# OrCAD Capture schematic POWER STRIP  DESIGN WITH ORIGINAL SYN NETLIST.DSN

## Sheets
1 PAGE2: size Custom; title: Power Micro Board; rev: <A>; note: Power Micro Board
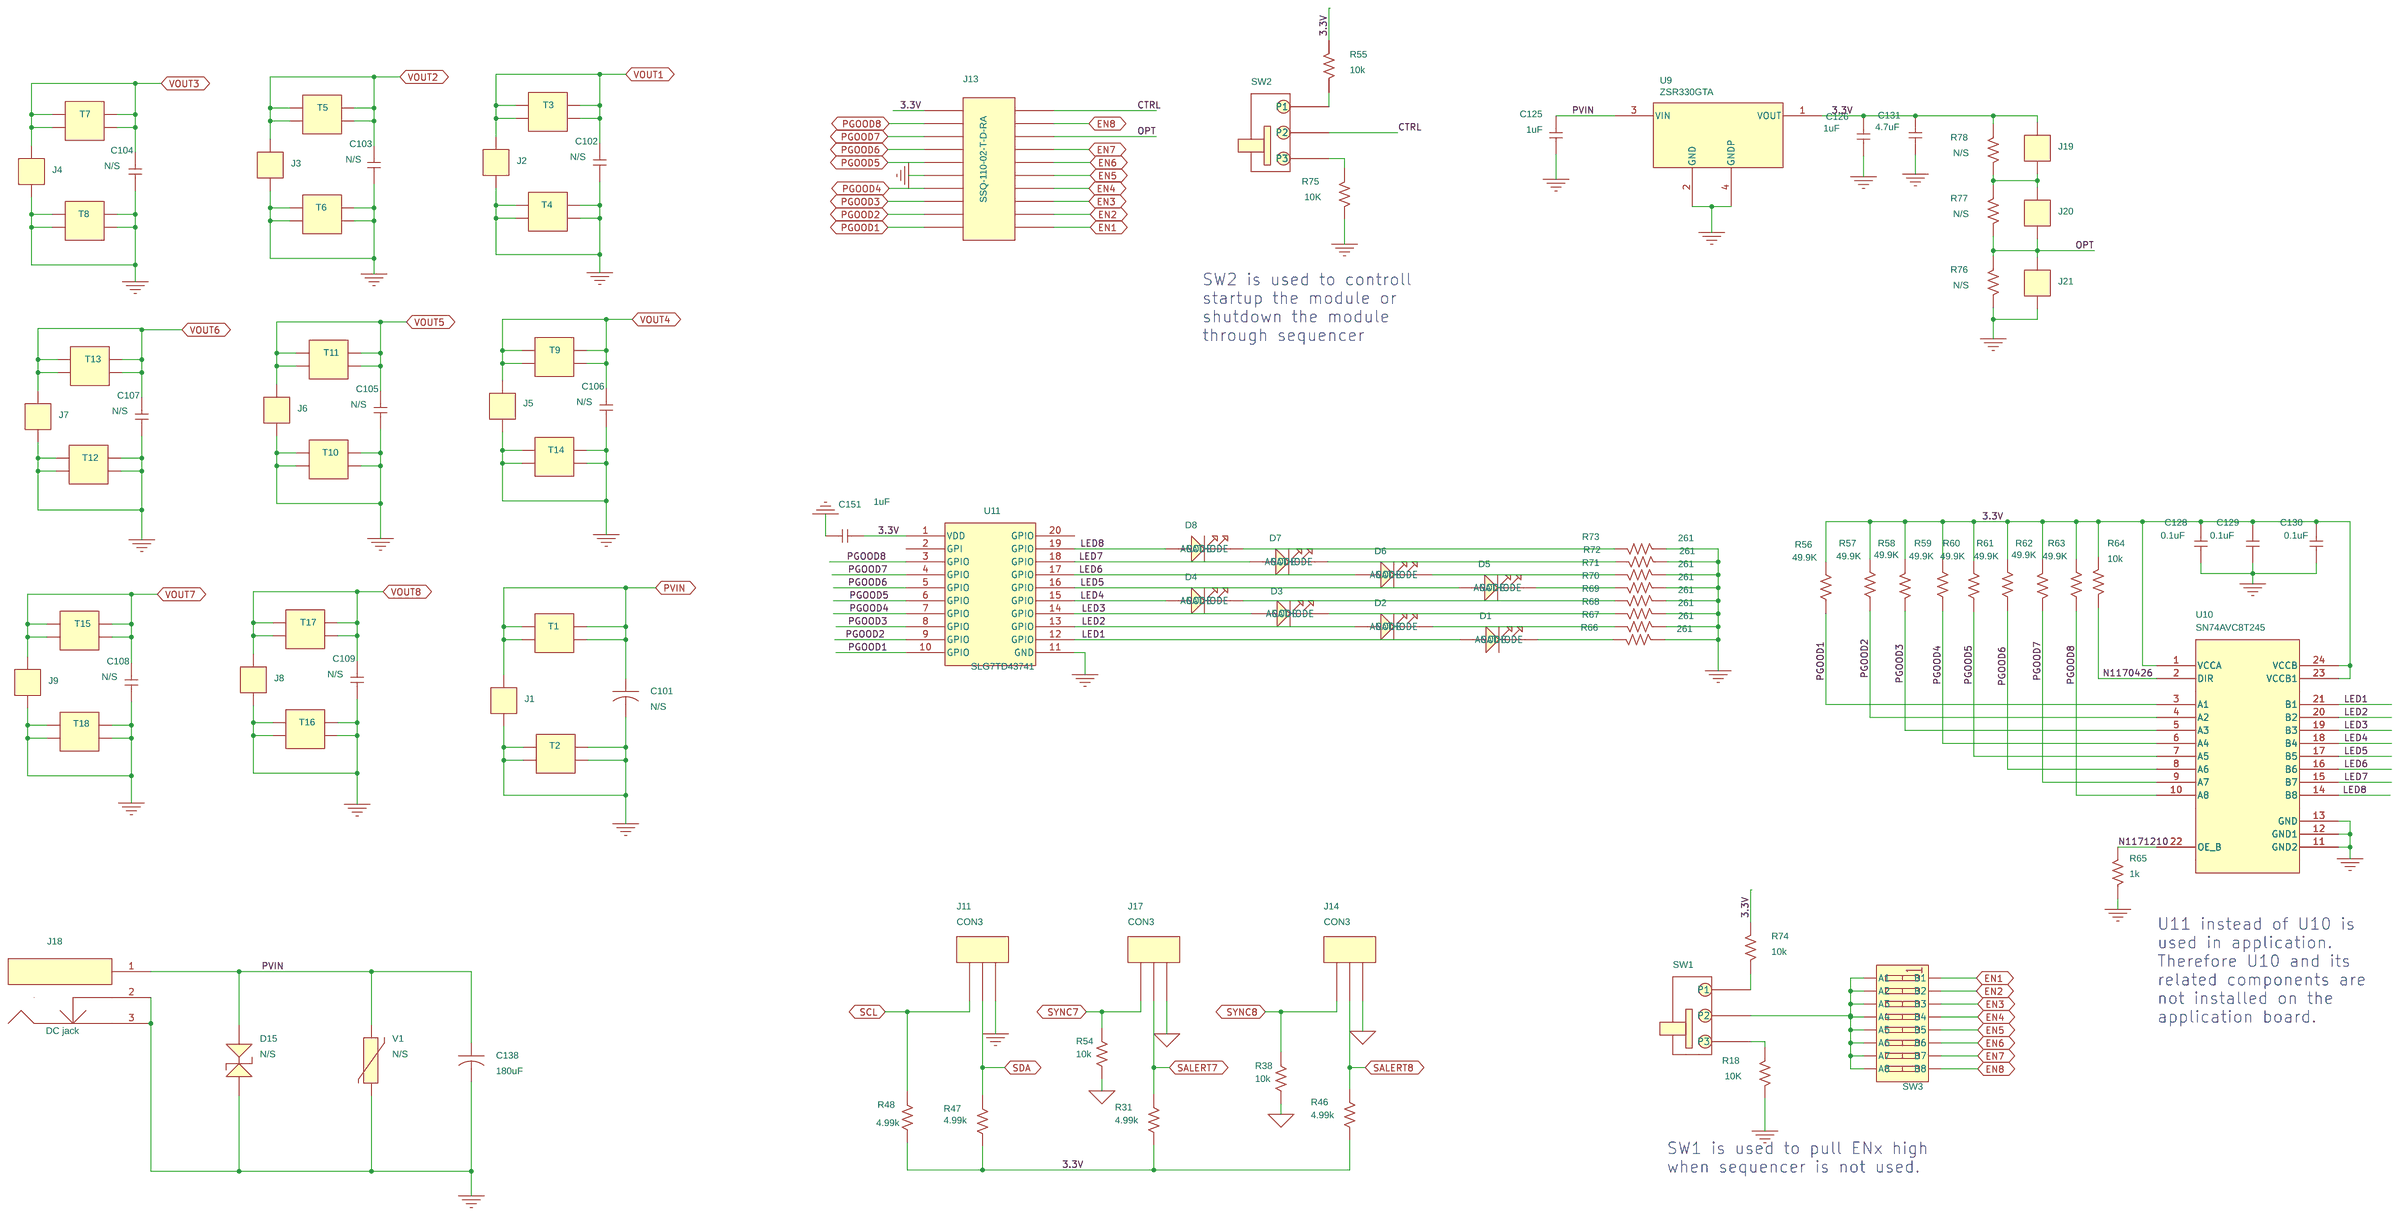
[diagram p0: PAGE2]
2 PAGE1: size Custom; rev: A
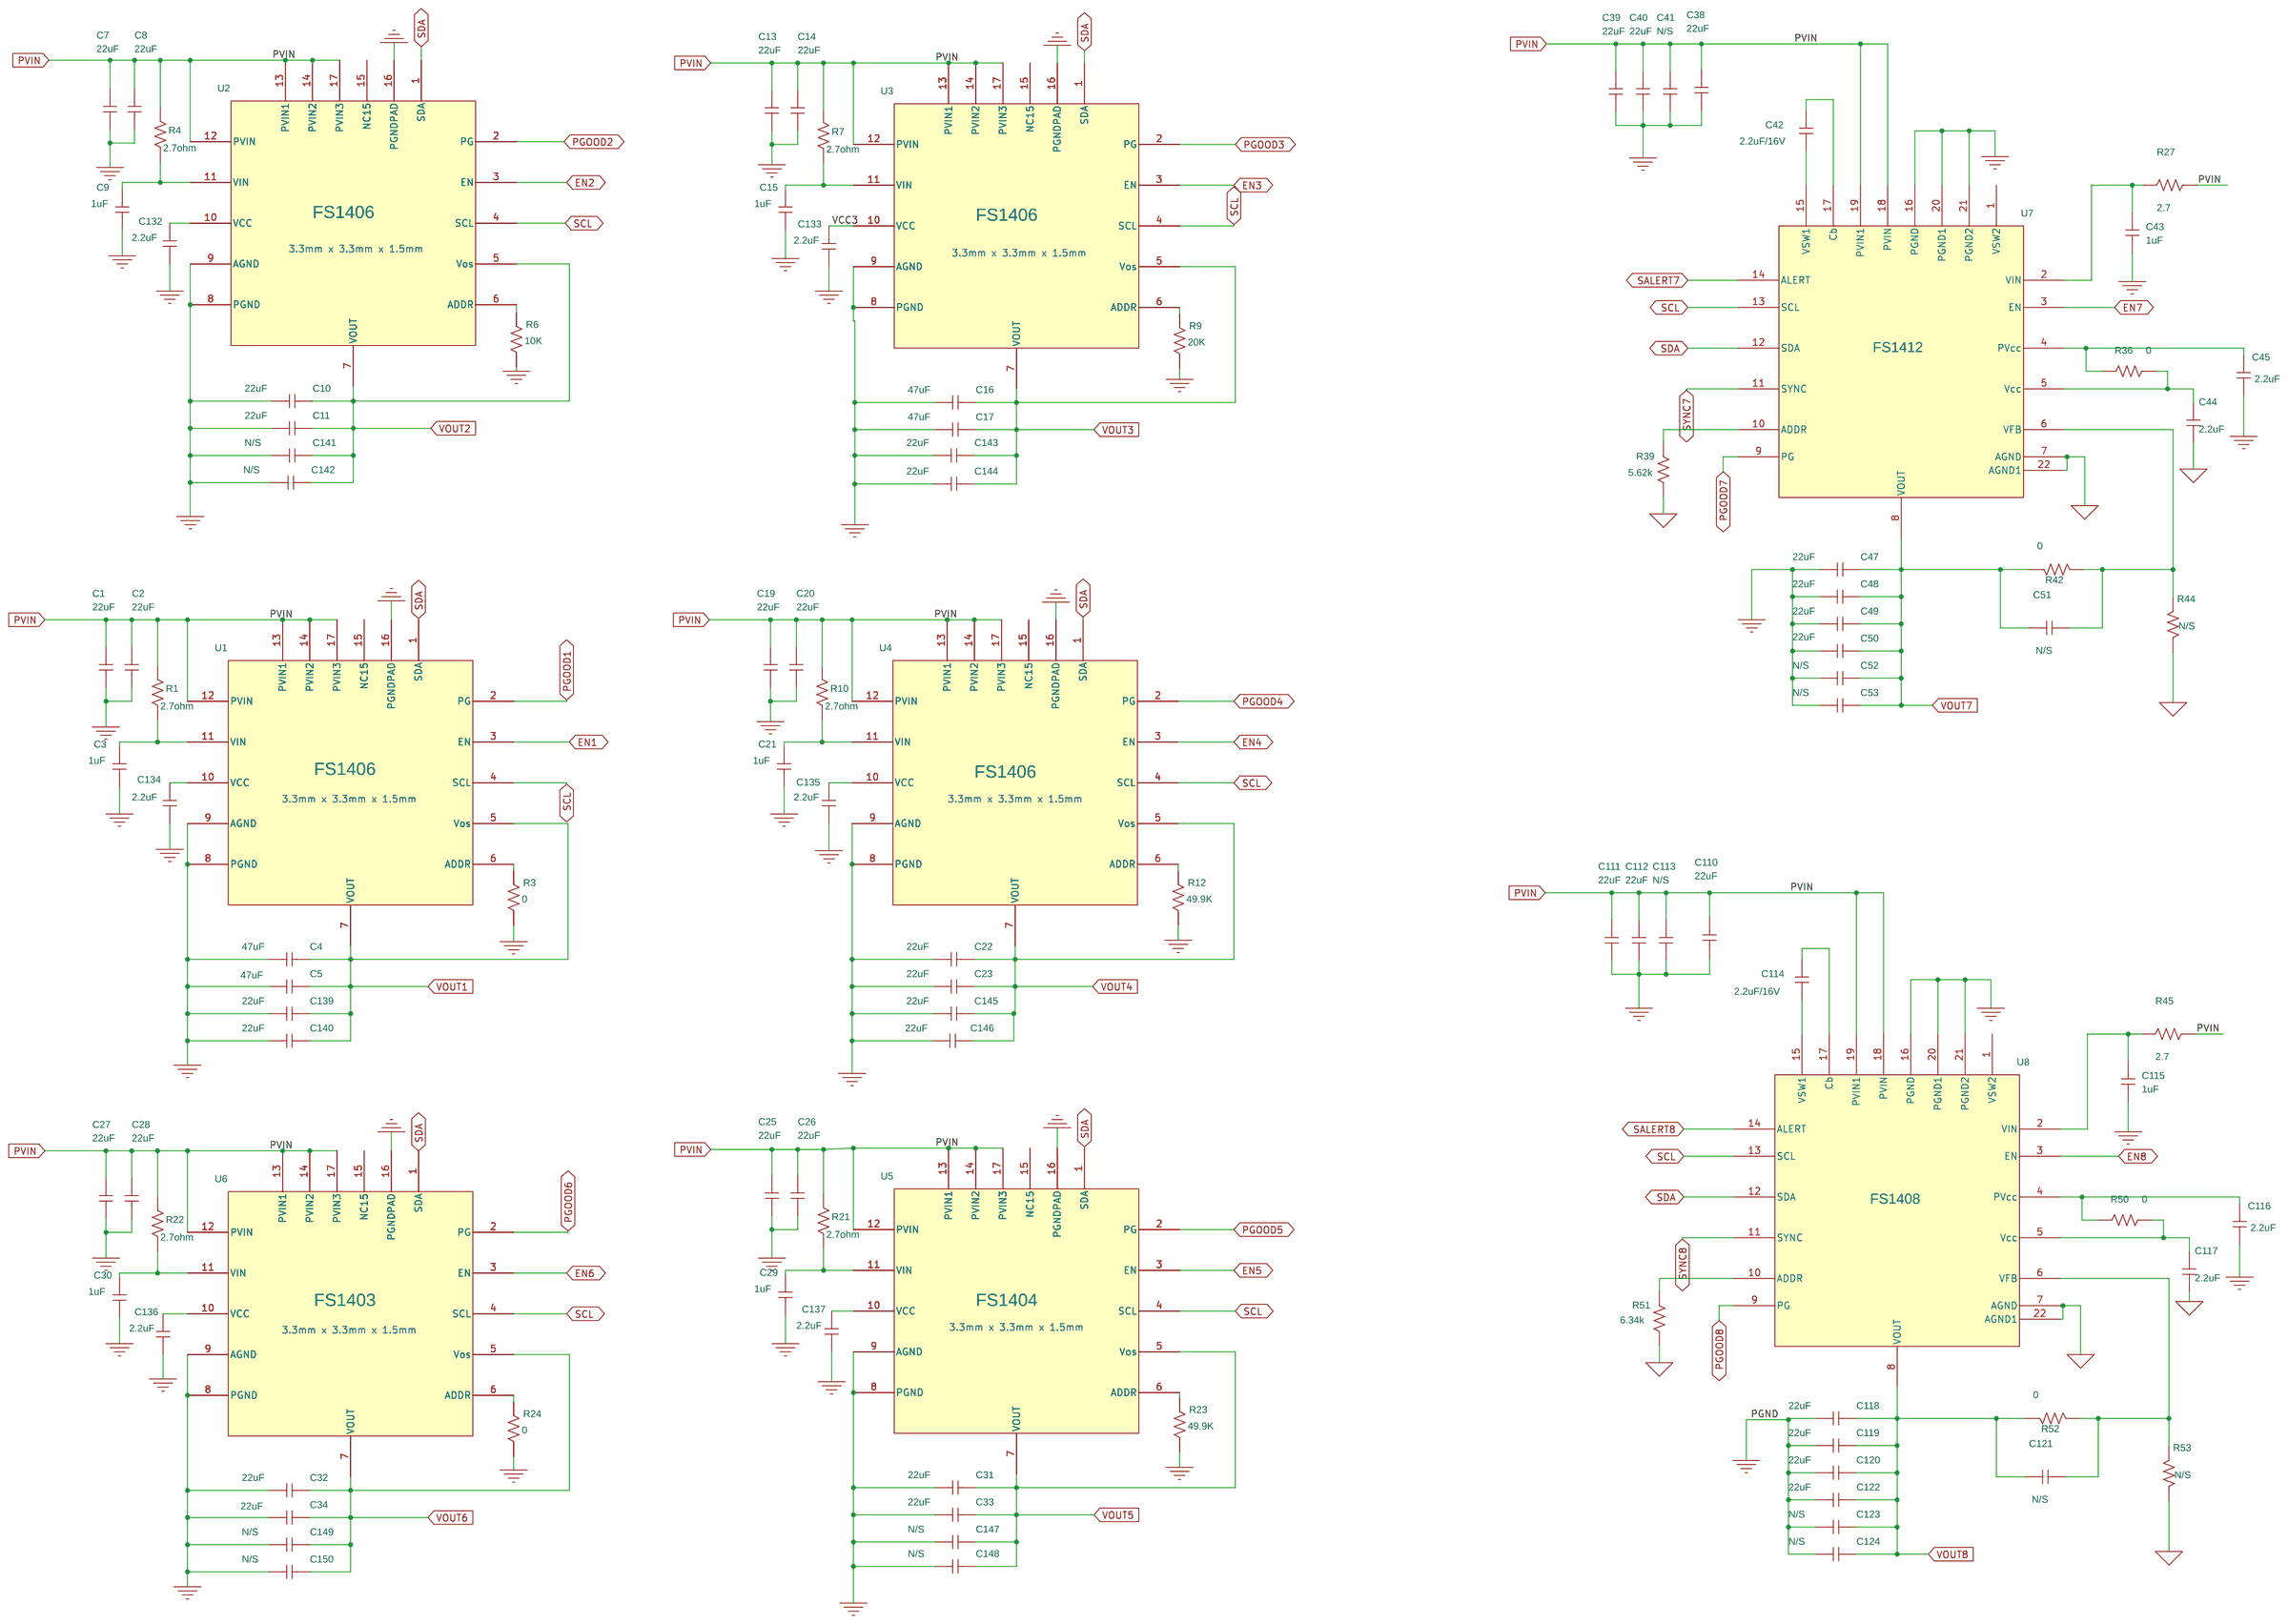
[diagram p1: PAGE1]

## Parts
sheet PAGE1
C1  22uF  [0805]
C2  22uF  [0805]
C3  1uF  [0603]
C4  47uF  [0805]
C5  47uF  [0805]
C7  22uF  [0805]
C8  22uF  [0805]
C9  1uF  [0603]
C10  22uF  [0805]
C11  22uF  [0805]
C13  22uF  [0805]
C14  22uF  [0805]
C15  1uF  [0603]
C16  47uF  [0805]
C17  47uF  [0805]
C19  22uF  [0805]
C20  22uF  [0805]
C21  1uF  [0603]
C22  22uF  [0805]
C23  22uF  [0805]
C25  22uF  [0805]
C26  22uF  [0805]
C27  22uF  [0805]
C28  22uF  [0805]
C29  1uF  [0603]
C30  1uF  [0603]
C31  22uF  [0805]
C32  22uF  [0805]
C33  22uF  [0805]
C34  22uF  [0805]
C38  22uF  [0805]
C39  22uF  [0805]
C40  22uF  [0805]
C41  N/S  [0805]
C42  2.2uF/16V  [0603]
C43  1uF  [0603]
C44  2.2uF  [0402]
C45  2.2uF  [0402]
C47  22uF  [0805]
C48  22uF  [0805]
C49  22uF  [0805]
C50  22uF  [0805]
C51  N/S  [0402]
C52  N/S  [0805]
C53  N/S  [0805]
C110  22uF  [0805]
C111  22uF  [0805]
C112  22uF  [0805]
C113  N/S  [0805]
C114  2.2uF/16V  [0603]
C115  1uF  [0603]
C116  2.2uF  [0402]
C117  2.2uF  [0402]
C118  22uF  [0805]
C119  22uF  [0805]
C120  22uF  [0805]
C121  N/S  [0402]
C122  22uF  [0805]
C123  N/S  [0805]
C124  N/S  [0805]
C132  2.2uF  [0402]
C133  2.2uF  [0402]
C134  2.2uF  [0402]
C135  2.2uF  [0402]
C136  2.2uF  [0402]
C137  2.2uF  [0402]
C139  22uF  [0805]
C140  22uF  [0805]
C141  N/S  [0805]
C142  N/S  [0805]
C143  22uF  [0805]
C144  22uF  [0805]
C145  22uF  [0805]
C146  22uF  [0805]
C147  N/S  [0805]
C148  N/S  [0805]
C149  N/S  [0805]
C150  N/S  [0805]
R1  2.7ohm  [0402]
R3  0  [0402]
R4  2.7ohm  [0402]
R6  10K  [0402]
R7  2.7ohm  [0402]
R9  20K  [0402]
R10  2.7ohm  [0402]
R12  49.9K  [0402]
R21  2.7ohm  [0402]
R22  2.7ohm  [0402]
R23  49.9K  [0402]
R24  0  [0402]
R27  2.7  [0402]
R36  0  [0402]
R39  5.62k  [0402]
R42  0  [0402]
R44  N/S  [0402]
R45  2.7  [0402]
R50  0  [0402]
R51  6.34k  [0402]
R52  0  [0402]
R53  N/S  [0402]
U1  FS1406  [FS1406-02_NEW]
U2  FS1406  [FS1406-02_NEW]
U3  FS1406  [FS1406-02_NEW]
U4  FS1406  [FS1406-02_NEW]
U5  FS1404  [FS1406-02_NEW]
U6  FS1403  [FS1406-02_NEW]
U7  FS1412  [FS1412-POD]
U8  FS1408  [FS1412-POD]
sheet PAGE2
C101  N/S  [C10_CAP]
C102  N/S  [0603]
C103  N/S  [0603]
C104  N/S  [0603]
C105  N/S  [0603]
C106  N/S  [0603]
C107  N/S  [0603]
C108  N/S  [0603]
C109  N/S  [0603]
C125  1uF  [0603]
C126  1uF  [0603]
C128  0.1uF  [C0603]
C129  0.1uF  [C0402]
C130  0.1uF  [C0402]
C131  4.7uF  [0603]
C138  180uF  [C10_CAP]
C151  1uF  [0402]
D1  LED-GRN-SMT  [SML-LX0603]
D2  LED-GRN-SMT  [SML-LX0603]
D3  LED-GRN-SMT  [SML-LX0603]
D4  LED-GRN-SMT  [SML-LX0603]
D5  LED-GRN-SMT  [SML-LX0603]
D6  LED-GRN-SMT  [SML-LX0603]
D7  LED-GRN-SMT  [SML-LX0603]
D8  LED-GRN-SMT  [SML-LX0603]
D15  N/S  [DO-214AC_BI]
J1  CON2  [HDR1X2]
J2  CON2  [HDR1X2]
J3  CON2  [HDR1X2]
J4  CON2  [HDR1X2]
J5  CON2  [HDR1X2]
J6  CON2  [HDR1X2]
J7  CON2  [HDR1X2]
J8  CON2  [HDR1X2]
J9  CON2  [HDR1X2]
J11  CON3  [HDR1X3]
J13  SSQ-110-02-T-D-RA  [SSQ-110-02-T-D-RA]
J14  CON3  [HDR1X3]
J17  CON3  [HDR1X3]
J18  DC jack  [PJ-058A]
J19  CON2  [HDR1X2]
J20  CON2  [HDR1X2]
J21  CON2  [HDR1X2]
R18  10K  [0402]
R31  4.99k  [0402]
R38  10k  [0402]
R46  4.99k  [0402]
R47  4.99k  [0402]
R48  4.99k  [0402]
R54  10k  [0402]
R55  10k  [0402]
R56  49.9K  [R0402]
R57  49.9K  [R0402]
R58  49.9K  [R0402]
R59  49.9K  [R0402]
R60  49.9K  [R0402]
R61  49.9K  [R0402]
R62  49.9K  [R0402]
R63  49.9K  [R0402]
R64  10k  [R0402]
R65  1k  [R0402]
R66  261  [0402]
R67  261  [0402]
R68  261  [0402]
R69  261  [0402]
R70  261  [0402]
R71  261  [0402]
R72  261  [0402]
R73  261  [0402]
R74  10k  [0402]
R75  10K  [0402]
R76  N/S  [0402]
R77  N/S  [0402]
R78  N/S  [0402]
SW1  1101M2S3CQE2  [1101M1S3CQE2]
SW2  1101M2S3CQE2  [1101M1S3CQE2]
SW3  SW_DIP_8POS  [219-8MST]
T1  TERM BLOCK 1 PIN-Keystone_sm  [7693]
T2  TERM BLOCK 1 PIN-Keystone_sm  [7693]
T3  TERM BLOCK 1 PIN-Keystone_sm  [7693]
T4  TERM BLOCK 1 PIN-Keystone_sm  [7693]
T5  TERM BLOCK 1 PIN-Keystone_sm  [7693]
T6  TERM BLOCK 1 PIN-Keystone_sm  [7693]
T7  TERM BLOCK 1 PIN-Keystone_sm  [7693]
T8  TERM BLOCK 1 PIN-Keystone_sm  [7693]
T9  TERM BLOCK 1 PIN-Keystone_sm  [7693]
T10  TERM BLOCK 1 PIN-Keystone_sm  [7693]
T11  TERM BLOCK 1 PIN-Keystone_sm  [7693]
T12  TERM BLOCK 1 PIN-Keystone_sm  [7693]
T13  TERM BLOCK 1 PIN-Keystone_sm  [7693]
T14  TERM BLOCK 1 PIN-Keystone_sm  [7693]
T15  TERM BLOCK 1 PIN-Keystone_sm  [7693]
T16  TERM BLOCK 1 PIN-Keystone_sm  [7693]
T17  TERM BLOCK 1 PIN-Keystone_sm  [7693]
T18  TERM BLOCK 1 PIN-Keystone_sm  [7693]
U9  ZSR330GTA  [SOT223]
U10  SN74AVC8T245  [TSSOP_24]
U11  SLG7TD43741  [STQFN20]
V1  N/S  [AVR]

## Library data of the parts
C1 C2 C7 C8 C13 C14 C19 C20 C25-C28 = C: 22uF-0805-16V-X5R-10%; Manufacturer: TDK; Part Number: C2012X5R1C226K125AC
C3 C9 C15 C21 C29 C30 C43 C102-C109 C115 C125 C126 C131 = C: 1uF-0603-25V-X5R-10%; Manufacturer: Samsung; Part Number: CL10A105KA8NNNC
C4 C5 C16 C17 = C: 47uF-0805-6.3V-X5R-20%; Manufacturer: TDK; Part Number: C2012X5R0J476M125AC
C10 = C: 22uF-0805-6.3V-X5R-10%; Manufacturer: TDK; Part Number: C2012X5R0J226K125AB; VOLTAGE: CMAX
C11 C22 C23 C31-C34 C47-C50 C52 C53 C118-C120 C122-C124 C139-C150 = C: 22uF-0805-6.3V-X5R-10%; Manufacturer: TDK; Part Number: C2012X5R0J226K125AB
C38-C41 C110-C113 = C: 22uF-0805-25V-X5R-10%; Manufacturer: TDK; Part Number: C2012X5R1E226M125AC
C42 C44 C45 C51 C114 C116 C117 C121 = C
C132-C137 = C: 2.2uF-0402-10V-X7S-10%
R1 R4 R7 R10 R21 R22 R27 R45 = R: Res,0402,1/10 W,5%; Manufacturer: Panasonic; Part Number: ERJ-2GEJ2R7X
R3 R24 = R: Res,0402,1/16 W,1%; Manufacturer: Panasonic; Part Number: ERJ-2GE0R00X
R6 = R: Res,0402,1/10 W,1%; Manufacturer: Panasonic; Part Number: ERJ-2RKF1002X
R9 = R: Res,0402,1/10 W,1%; Manufacturer: Panasonic; Part Number: ERJ-2RKF2002X
R12 R23 R56-R63 = R: Res,0402,1/10 W,1%; Manufacturer: Panasonic; Part Number: ERJ-2RKF4992X
R31 R36 R42 R44 R46-R48 R50 R52 R53 R64 R74 = R
R39 R51 = R: Res,0402,1/16 W,1%; Manufacturer: Panasonic
U1 = FS1206_18
U2 = FS1206_16
U3 = FS1206_17
U4 = FS1206_19
U5 = FS1206_21
U6 = FS1206_20
U7 U8 = FS1206_11
C101 C138 = CAP: 180uF Elecrolytic; ESR(mOhms): 22m; Manufacturer: Sanyo; Part Number: 16SVPE180M; Ripple Current: 4460mA; Voltage: 16V
C128 C130 = C: 1uF-0402-25V-X7R-10%; Manufacturer: TDK; Part Number: TMK105B7104KVHF
C129 = C: 1uF-0402-25V-X7%; Manufacturer: TDK; Part Number: TMK105B7104KVHF
C151 = C: 1uF-0402-25V-X5R-10%; Manufacturer: TDK; Part Number: TMK105B7104KVHF
D1-D8 = LN411YP: LED 565NM GREEN DIFF 0603 SMD; DEVICE: LED-GRN-SMT_LED_0603; MANF: LUMEX; MANF_P/N: SML-LX0603GW-TR
D15 = DIODE_ZENER_3: Part Number: SMAJ17CA
J1-J9 J19-J21 = CON3_9: Header,1x2,TH,0.025 Sq,0.1inch Space; Manufacturer: Harwin; Part Number: M20-9990246
J11 J14 J17 = CON3: Header,1x3,TH,0.025 Sq,0.1inch Space; Manufacturer: Harwin; Part Number: M20-9990346
J13 = CON3_12: CONN RCPT 20POS 0.1 TIN PCB R/A; DEVICE: HDR_2X10
J18 = power_jack: Power Jack
R18 R38 R54 R55 R75 R76 = R: Res,0402,1/10 W,1%; Part Number: ERJ-2RKF1002X
R65 = R: MANF_P/N: MCR01MZPF1001; PartType: SMT - 1%
R66-R73 = R: MANF_P/N: ERJ-2RKF2610X; POWER: 1/10W; PartType: SMT - 1%; TOLERANCE: 1%
R77 R78 = R: Res,0402,1/10 W,1%; Part Number: ERJ-2RKF1272X
SW1 SW2 = SW_SLIDE_SPDT_1: SWITCH SLIDE MINI SPDT R/A BK; Manufacturer: C&K; PartType: SPDT; ROHS: Yes
SW3 = SW_DIP_1
T1-T18 = CON3_11: Term. Block,1 Pos,15A,300V; Manufacturer: Keystone
U9 = LT1085_2: LDO
U10 = SN74AVC8T245_1: 8-BIT DUAL SUPPLY LEVEL TRANSLATOR; Barcode: 500014; Family: BUS TRANSCEIVER; MANF: TI; MANF_P/N: SN74AVC8T245PWR; ROHS: Yes; Voltage: 1.2V; Datasheet: \\XSJ-SMB\AFX\AFX\BOARD_PROJECTS\LIBRARY\DATASHEETS\IC\DATA COMM\SN74AVC8T245.pdf
U11 = SLG46722
V1 = DIODE_ZENER_4: Part Number: AVR-M2012C220KT6AB

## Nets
3.3V: C126.2 C128.2 C129.2 C130.2 C131.2 C151.1 J13.1 J19.1 R31.2 R46.2 R47.2 R48.2 R55.2 R56.2 R57.2 R58.1 R59.2 R60.2 R61.2 R62.1 R63.2 R64.2 R74.2 R78.1 U9.1(VOUT) U10.1(VCCA) U10.23(VCCB1) U10.24(VCCB) U11.1(VDD)
AGND1: C44.1 J17.3 R39.2 R44.1 R54.2 U7.7(AGND) U7.22(AGND1)
AGND2: C117.1 J14.3 R38.2 R51.2 R53.1 U8.7(AGND) U8.22(AGND1)
PGND: C1.1 C2.1 C3.1 C4.2 C5.2 C7.1 C8.1 C9.1 C10.2 C11.2 C13.1 C14.1 C15.1 C16.2 C17.2 C19.1 C20.1 C21.1 C22.2 C23.2 C25.1 C26.1 C27.1 C28.1 C29.1 C30.1 C31.2 C32.2 C33.2 C34.2 C38.1 C39.1 C40.1 C41.1 C43.1 C45.1 C47.2 C48.2 C49.2 C50.2 C52.2 C53.2 C101.2 C102.1 C103.1 C104.1 C105.1 C106.1 C107.1 C108.1 C109.1 C110.1 C111.1 C112.1 C113.1 C115.1 C116.1 C118.2 C119.2 C120.2 C122.2 C123.2 C124.2 C125.1 C126.1 C128.1 C129.1 C130.1 C131.1 C132.1 C133.1 C134.1 C135.1 C136.1 C137.1 C138.2 C139.2 C140.2 C141.2 C142.2 C143.2 C144.2 C145.2 C146.2 C147.2 C148.2 C149.2 C150.2 C151.2 D15.1 J1.2 J2.2 J3.2 J4.2 J5.2 J6.2 J7.2 J8.2 J9.2 J11.3 J13.11 J18.2 J18.3 J21.2 R3.1 R6.1 R9.1 R12.1 R18.2 R23.1 R24.1 R65.1 R66.1 R67.1 R68.1 R69.1 R70.1 R71.1 R72.1 R73.1 R75.2 R76.2 T2.1 T2.2 T2.3 T2.4 T4.1 T4.2 T4.3 T4.4 T6.1 T6.2 T6.3 T6.4 T8.1 T8.2 T8.3 T8.4 T10.1 T10.2 T10.3 T10.4 T12.1 T12.2 T12.3 T12.4 T14.1 T14.2 T14.3 T14.4 T16.1 T16.2 T16.3 T16.4 T18.1 T18.2 T18.3 T18.4 U1.8(PGND) U1.9(AGND) U1.16(PGNDPAD) U2.8(PGND) U2.9(AGND) U2.16(PGNDPAD) U3.8(PGND) U3.9(AGND) U3.16(PGNDPAD) U4.8(PGND) U4.9(AGND) U4.16(PGNDPAD) U5.8(PGND) U5.9(AGND) U5.16(PGNDPAD) U6.8(PGND) U6.9(AGND) U6.16(PGNDPAD) U7.16(PGND) U7.20(PGND1) U7.21(PGND2) U8.16(PGND) U8.20(PGND1) U8.21(PGND2) U9.2(GND) U9.4(GNDP) U10.11(GND2) U10.12(GND1) U10.13(GND) U11.11(GND) V1.1
PVIN: C1.2 C2.2 C7.2 C8.2 C13.2 C14.2 C19.2 C20.2 C25.2 C26.2 C27.2 C28.2 C38.2 C39.2 C40.2 C41.2 C101.1 C110.2 C111.2 C112.2 C113.2 C125.2 C138.1 D15.2 J1.1 J18.1 R1.2 R4.2 R7.2 R10.2 R21.2 R22.2 R27.1 R45.1 T1.1 T1.2 T1.3 T1.4 U1.12(PVIN) U1.13(PVIN1) U1.14(PVIN2) U1.17(PVIN3) U2.12(PVIN) U2.13(PVIN1) U2.14(PVIN2) U2.17(PVIN3) U3.12(PVIN) U3.13(PVIN1) U3.14(PVIN2) U3.17(PVIN3) U4.12(PVIN) U4.13(PVIN1) U4.14(PVIN2) U4.17(PVIN3) U5.12(PVIN) U5.13(PVIN1) U5.14(PVIN2) U5.17(PVIN3) U6.12(PVIN) U6.13(PVIN1) U6.14(PVIN2) U6.17(PVIN3) U7.18(PVIN) U7.19(PVIN1) U8.18(PVIN) U8.19(PVIN1) U9.3(VIN) V1.2
VCC3: C133.2 U3.10(VCC)
CTRL: J13.2 SW2.2(P2)
EN1: J13.20 SW3.1(B1) U1.3(EN)
EN2: J13.18 SW3.2(B2) U2.3(EN)
EN3: J13.16 SW3.3(B3) U3.3(EN)
EN4: J13.14 SW3.4(B4) U4.3(EN)
EN5: J13.12 SW3.5(B5) U5.3(EN)
EN6: J13.10 SW3.6(B6) U6.3(EN)
EN7: J13.8 SW3.7(B7) U7.3(EN)
EN8: J13.4 SW3.8(B8) U8.3(EN)
GPI: U11.2(GPI)
GPIO: U11.20(GPIO)
LED1: D1.1(ANODE) U10.21(B1) U11.12(GPIO)
LED2: D2.1(ANODE) U10.20(B2) U11.13(GPIO)
LED3: D3.1(ANODE) U10.19(B3) U11.14(GPIO)
LED4: D4.1(ANODE) U10.18(B4) U11.15(GPIO)
LED5: D5.1(ANODE) U10.17(B5) U11.16(GPIO)
LED6: D6.1(ANODE) U10.16(B6) U11.17(GPIO)
LED7: D7.1(ANODE) U10.15(B7) U11.18(GPIO)
LED8: D8.1(ANODE) U10.14(B8) U11.19(GPIO)
OPT: J13.6 J20.2 J21.1 R76.1 R77.2
PGOOD1: J13.19 R56.1 U1.2(PG) U10.3(A1) U11.10(GPIO)
PGOOD2: J13.17 R57.1 U2.2(PG) U10.4(A2) U11.9(GPIO)
PGOOD3: J13.15 R58.2 U3.2(PG) U10.5(A3) U11.8(GPIO)
PGOOD4: J13.13 R59.1 U4.2(PG) U10.6(A4) U11.7(GPIO)
PGOOD5: J13.9 R60.1 U5.2(PG) U10.7(A5) U11.6(GPIO)
PGOOD6: J13.7 R61.1 U6.2(PG) U10.8(A6) U11.5(GPIO)
PGOOD7: J13.5 R62.2 U7.9(PG) U10.9(A7) U11.4(GPIO)
PGOOD8: J13.3 R63.1 U8.9(PG) U10.10(A8) U11.3(GPIO)
SALERT7: J17.2 R31.1 U7.14(ALERT)
SALERT8: J14.2 R46.1 U8.14(ALERT)
SCL: J11.1 R48.1 U1.4(SCL) U2.4(SCL) U3.4(SCL) U4.4(SCL) U5.4(SCL) U6.4(SCL) U7.13(SCL) U8.13(SCL)
SDA: J11.2 R47.1 U1.1(SDA) U2.1(SDA) U3.1(SDA) U4.1(SDA) U5.1(SDA) U6.1(SDA) U7.12(SDA) U8.12(SDA)
SYNC7: J17.1 R54.1 U7.11(SYNC)
SYNC8: J14.1 R38.1 U8.11(SYNC)
VOUT1: C4.1 C5.1 C102.2 C139.1 C140.1 J2.1 T3.1 T3.2 T3.3 T3.4 U1.5(Vos) U1.7(VOUT)
VOUT2: C10.1 C11.1 C103.2 C141.1 C142.1 J3.1 T5.1 T5.2 T5.3 T5.4 U2.5(Vos) U2.7(VOUT)
VOUT3: C16.1 C17.1 C104.2 C143.1 C144.1 J4.1 T7.1 T7.2 T7.3 T7.4 U3.5(Vos) U3.7(VOUT)
VOUT4: C22.1 C23.1 C106.2 C145.1 C146.1 J5.1 T9.1 T9.2 T9.3 T9.4 U4.5(Vos) U4.7(VOUT)
VOUT5: C31.1 C33.1 C105.2 C147.1 C148.1 J6.1 T11.1 T11.2 T11.3 T11.4 U5.5(Vos) U5.7(VOUT)
VOUT6: C32.1 C34.1 C107.2 C149.1 C150.1 J7.1 T13.1 T13.2 T13.3 T13.4 U6.5(Vos) U6.7(VOUT)
VOUT7: C47.1 C48.1 C49.1 C50.1 C51.1 C52.1 C53.1 C108.2 J9.1 R42.1 T15.1 T15.2 T15.3 T15.4 U7.8(VOUT)
VOUT8: C109.2 C118.1 C119.1 C120.1 C121.1 C122.1 C123.1 C124.1 J8.1 R52.1 T17.1 T17.2 T17.3 T17.4 U8.8(VOUT)
N106541: C9.2 R4.1 U2.11(VIN)
N109036: C132.2 U2.10(VCC)
N111800: C15.2 R7.1 U3.11(VIN)
N112773: C3.2 R1.1 U1.11(VIN)
N113813: C21.2 R10.1 U4.11(VIN)
N124020: R6.2 U2.6(ADDR)
N125365: R3.2 U1.6(ADDR)
N125599: R12.2 U4.6(ADDR)
N125833: R9.2 U3.6(ADDR)
N143732: C29.2 R21.1 U5.11(VIN)
N143740: C30.2 R22.1 U6.11(VIN)
N143880: R23.2 U5.6(ADDR)
N143888: R24.2 U6.6(ADDR)
N983153: C42.2 U7.17(Cb)
N983255: C42.1 U7.15(VSW1)
N983335: C43.2 R27.2 U7.2(VIN)
N983701: C45.2 R36.2 U7.4(PVcc)
N983781: C44.2 R36.1 U7.5(Vcc)
N983905: R39.1 U7.10(ADDR)
N983923: C51.2 R42.2 R44.2 U7.6(VFB)
N1133327: C114.2 U8.17(Cb)
N1133411: C114.1 U8.15(VSW1)
N1133439: C115.2 R45.2 U8.2(VIN)
N1133683: C116.2 R50.2 U8.4(PVcc)
N1133735: C117.2 R50.1 U8.5(Vcc)
N1133791: R51.1 U8.10(ADDR)
N1133799: C121.2 R52.2 R53.2 U8.6(VFB)
N1144589: SW1.2(P2) SW3.9(A8) SW3.10(A7) SW3.11(A6) SW3.12(A5) SW3.13(A4) SW3.14(A3) SW3.15(A2) SW3.16(A1)
N1166950: R75.1 SW2.3(P3)
N1167645: R55.1 SW2.1(P1)
N1170426: R64.1 U10.2(DIR)
N1170926: D5.2(CATHODE) R70.2
N1170982: D4.2(CATHODE) R69.2
N1171050: D3.2(CATHODE) R68.2
N1171118: D2.2(CATHODE) R67.2
N1171178: D1.2(CATHODE) R66.2
N1171210: R65.2 U10.22(OE_B)
N1176310: D6.2(CATHODE) R71.2
N1183669: D8.2(CATHODE) R73.2
N1183969: D7.2(CATHODE) R72.2
N1197737: R74.1 SW1.1(P1)
N1197747: R18.1 SW1.3(P3)
N1234759: C134.2 U1.10(VCC)
N1235035: C135.2 U4.10(VCC)
N1235784: C136.2 U6.10(VCC)
N1236304: C137.2 U5.10(VCC)
N1413705: J19.2 J20.1 R77.1 R78.2

Not connected (* = marked no-connect by the designer): U1 15(NC15); U2 15(NC15); U3 15(NC15); U4 15(NC15); U5 15(NC15); U6 15(NC15); U7 1(VSW2); U8 1(VSW2)

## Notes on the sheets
sheet 1
- SW2 is used to controll
  startup the module or
  shutdown the module
  through sequencer
- U11 instead of U10 is
  used in application.
  Therefore U10 and its
  related components are
  not installed on the
  application board.
- SW1 is used to pull ENx high
  when sequencer is not used.
sheet 2
- 3.3mm x 3.3mm x 1.5mm
- 3.3mm x 3.3mm x 1.5mm
- 3.3mm x 3.3mm x 1.5mm
- 3.3mm x 3.3mm x 1.5mm
- 3.3mm x 3.3mm x 1.5mm
- 3.3mm x 3.3mm x 1.5mm
